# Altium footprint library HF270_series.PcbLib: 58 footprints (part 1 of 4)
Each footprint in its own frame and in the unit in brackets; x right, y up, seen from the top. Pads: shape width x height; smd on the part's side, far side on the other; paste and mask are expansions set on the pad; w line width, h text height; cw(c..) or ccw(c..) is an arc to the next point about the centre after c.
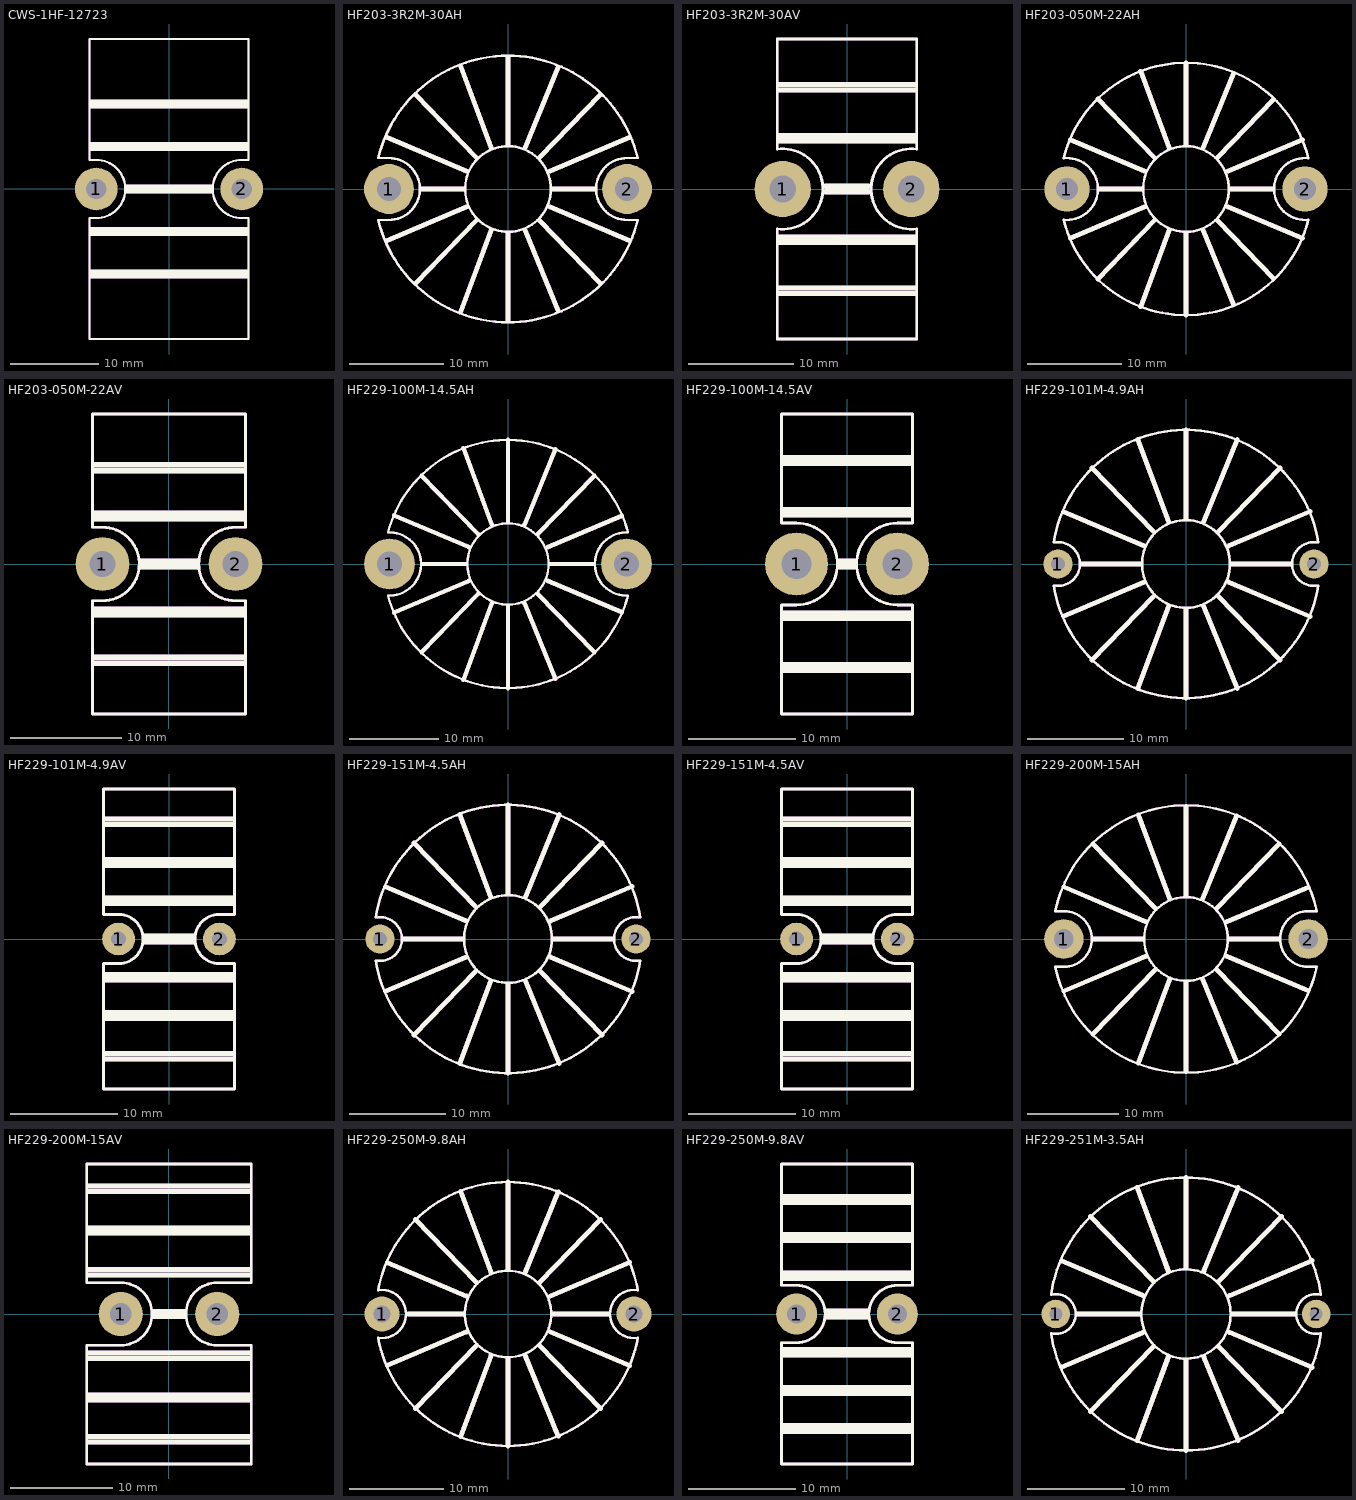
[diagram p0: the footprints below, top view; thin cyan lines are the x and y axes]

## CWS-1HF-12723 [mil]
pads (2):
  round 190 hole 90: 1(-325,0) 2(325,0)
Top Overlay:
  lines w10: -355,-670 -355,-130 -325,-130 ccw(c-325,0) -325,130 -355,130 -355,670 355,670 355,130 325,130 ccw(c325,0) 325,-130 355,-130 355,-670 -355,-670
  lines w19.68: -350,-390 350,-390 ; -350,-370 350,-370 ; -350,-200 350,-200 ; -350,-180 350,-180 ; -350,180 350,180 ; -350,200 350,200 ; -350,370 350,370 ; -350,390 350,390 ; -190,-10 190,-10 ; -190,10 190,10
Mechanical 29:
  lines w10: -355,-670 -355,-130 -325,-130 ccw(c-325,0) -325,130 -355,130 -355,670 355,670 355,130 325,130 ccw(c325,0) 325,-130 355,-130 355,-670 -355,-670
  lines w19.68: -350,-390 350,-390 ; -350,-370 350,-370 ; -350,-200 350,-200 ; -350,-180 350,-180 ; -350,180 350,180 ; -350,200 350,200 ; -350,370 350,370 ; -350,390 350,390 ; -190,-10 190,-10 ; -190,10 190,10
  text "'.Designator'" at -700,275.15 h400

## HF203-3R2M-30AH [mil]
pads (2):
  round 210 hole 100: 1(-500,0) 2(500,0)
Top Overlay:
  circle w10: c0,0 r180
  lines w10: -544.69,-130.06 ccw(c0,0) 544.45,-131.07 ; -544.69,130.06 cw(c0,0) 544.45,131.07 ; -544.45,-130 -500,-130 ccw(c-500,0) -500,130 -544.45,130 ; 544.45,-130 500,-130 cw(c500,0) 500,130 544.45,130
  lines w19.68: -509.12,-217.08 -173.05,-74.68 ; -509.12,217.08 -173.05,74.68 ; -388.47,-396.48 -132.7,-132.43 ; -388.47,396.48 -132.7,132.43 ; -365,0 -185,0 ; -198.53,-515.55 -70.44,-171.87 ; -198.53,515.55 -70.44,171.87 ; 0,-555 0,-185 ; 0,185 0,555 ; 72.46,-173.99 210.86,-511.7 ; 72.46,173.99 210.86,511.7 ; 132.5,-132.5 388.45,-396.51 ; 132.5,132.5 388.45,396.51 ; 175.3,-74.28 511.4,-216.7 ; 175.3,74.28 511.4,216.7 ; 185,0 365,0
Mechanical 29:
  circle w10: c0,0 r180
  lines w10: -544.69,-130.06 ccw(c0,0) 544.45,-131.07 ; -544.69,130.06 cw(c0,0) 544.45,131.07 ; -544.45,-130 -500,-130 ccw(c-500,0) -500,130 -544.45,130 ; 544.45,-130 500,-130 cw(c500,0) 500,130 544.45,130
  lines w19.68: -509.12,-217.08 -173.05,-74.68 ; -509.12,217.08 -173.05,74.68 ; -388.47,-396.48 -132.7,-132.43 ; -388.47,396.48 -132.7,132.43 ; -365,0 -185,0 ; -198.53,-515.55 -70.44,-171.87 ; -198.53,515.55 -70.44,171.87 ; 0,-555 0,-185 ; 0,185 0,555 ; 72.46,-173.99 210.86,-511.7 ; 72.46,173.99 210.86,511.7 ; 132.5,-132.5 388.45,-396.51 ; 132.5,132.5 388.45,396.51 ; 175.3,-74.28 511.4,-216.7 ; 175.3,74.28 511.4,216.7 ; 185,0 365,0
  text "'.Designator'" at -290,145.15 h400

## HF203-3R2M-30AV [mil]
pads (2):
  round 210 hole 100: 1(-240,0) 2(240,0)
Top Overlay:
  lines w10: -260.1,-148.65 ccw(c-240,0) -260,148.66 ; -260,-147.9 -260,-560 260,-560 260,-147.9 ; -260,147.9 -260,560 260,560 260,147.9 ; 260,-148.66 cw(c240,0) 260.1,148.65
  lines w19.68: -255,-390 255,-390 ; -255,-370 255,-370 ; -255,-200 255,-200 ; -255,-180 255,-180 ; -255,180 255,180 ; -255,200 255,200 ; -255,370 255,370 ; -255,390 255,390 ; -80,-10 80,-10 ; -80,10 80,10
Mechanical 29:
  lines w10: -260.1,-148.65 ccw(c-240,0) -260,148.66 ; -260,-147.9 -260,-560 260,-560 260,-147.9 ; -260,147.9 -260,560 260,560 260,147.9 ; 260,-148.66 cw(c240,0) 260.1,148.65
  lines w19.68: -255,-390 255,-390 ; -255,-370 255,-370 ; -255,-200 255,-200 ; -255,-180 255,-180 ; -255,180 255,180 ; -255,200 255,200 ; -255,370 255,370 ; -255,390 255,390 ; -80,-10 80,-10 ; -80,10 80,10
  text "'.Designator'" at -1750,-64.85 h400

## HF203-050M-22AH [mil]
pads (2):
  round 190 hole 93: 1(-500,0) 2(500,0)
Top Overlay:
  circle w10: c0,0 r180
  lines w10: -513.95,129.44 cw(c0,0) 513.58,130.91 ; -513.41,129.31 cw(c-500,0) -514,-129.24 ccw(c0,0) 514,-129.24 ; 513.41,129.31 ccw(c500,0) 514.25,-129.22
  lines w19.68: -486.13,-207.34 -173.05,-74.68 ; -486.13,207.34 -173.05,74.68 ; -371.29,-378.75 -132.7,-132.43 ; -371.29,378.75 -132.7,132.43 ; -365,0 -185,0 ; -190.76,-494.72 -70.44,-171.87 ; -190.76,494.72 -70.44,171.87 ; 0,-530 0,-185 ; 0,185 0,530 ; 72.46,-173.99 200.65,-486.78 ; 72.46,173.99 200.65,486.78 ; 132.5,-132.5 368.84,-376.28 ; 132.5,132.5 368.84,376.28 ; 175.3,-74.28 489.06,-207.23 ; 175.3,74.28 489.06,207.23 ; 185,0 365,0
Mechanical 29:
  circle w10: c0,0 r180
  lines w10: -513.95,129.44 cw(c0,0) 513.58,130.91 ; -513.41,129.31 cw(c-500,0) -514,-129.24 ccw(c0,0) 514,-129.24 ; 513.41,129.31 ccw(c500,0) 514.25,-129.22
  lines w19.68: -486.13,-207.34 -173.05,-74.68 ; -486.13,207.34 -173.05,74.68 ; -371.29,-378.75 -132.7,-132.43 ; -371.29,378.75 -132.7,132.43 ; -365,0 -185,0 ; -190.76,-494.72 -70.44,-171.87 ; -190.76,494.72 -70.44,171.87 ; 0,-530 0,-185 ; 0,185 0,530 ; 72.46,-173.99 200.65,-486.78 ; 72.46,173.99 200.65,486.78 ; 132.5,-132.5 368.84,-376.28 ; 132.5,132.5 368.84,376.28 ; 175.3,-74.28 489.06,-207.23 ; 175.3,74.28 489.06,207.23 ; 185,0 365,0
  text "'.Designator'" at -290,145.15 h400

## HF203-050M-22AV [mil]
pads (2):
  round 190 hole 93: 1(-235,0) 2(235,0)
Top Overlay:
  lines w10: -270,-130 -270,-530 270,-530 270,-130 ; -266,-130 -235,-130 ccw(c-235,0) -235,130 -270,130 -270,530 270,530 270,130 235,130 ccw(c235,0) 235,-130 266,-130
  lines w19.68: -265.5,-350 264.5,-350 ; -265.5,350 264.5,350 ; -265,-180 265,-180 ; -265,180 265,180 ; -264.5,-330 264.5,-330 ; -264.5,330 264.5,330 ; -264,-160 265,-160 ; -264,160 265,160 ; -101,-10 101,-10 ; -100,10 101,10
Mechanical 29:
  lines w10: -270,-130 -270,-530 270,-530 270,-130 ; -266,-130 -235,-130 ccw(c-235,0) -235,130 -270,130 -270,530 270,530 270,130 235,130 ccw(c235,0) 235,-130 266,-130
  lines w19.68: -265.5,-350 264.5,-350 ; -265.5,350 264.5,350 ; -265,-180 265,-180 ; -265,180 265,180 ; -264.5,-330 264.5,-330 ; -264.5,330 264.5,330 ; -264,-160 265,-160 ; -264,160 265,160 ; -101,-10 101,-10 ; -100,10 101,10
  text "'.Designator'" at -1750,-64.85 h400

## HF229-100M-14.5AH [mil]
pads (2):
  round 225 hole 110: 1(-525,0) 2(525,0)
Top Overlay:
  circle w10: c0,0 r180
  lines w10: -531.88,-140 ccw(c0,0) 531.43,-141.71 ; -531.88,140 cw(c0,0) 531.43,141.71 ; -531.34,-139.86 ccw(c-525,0) -531.34,139.86 ; 531.34,-139.86 cw(c525,0) 531.34,139.86
  lines w19.68: -504.88,-215.28 -173.05,-74.68 ; -504.88,215.28 -173.05,74.68 ; -383.55,-391.4 -132.7,-132.43 ; -383.55,391.4 -132.7,132.43 ; -380,0 -185,0 ; -197.92,-513.91 -70.44,-171.87 ; -197.92,513.91 -70.44,171.87 ; 0,-550 0,-185 ; 0,185 0,550 ; 72.46,-173.99 210.14,-509.94 ; 72.46,173.99 210.14,509.94 ; 132.5,-132.5 383.6,-391.51 ; 132.5,132.5 383.6,391.51 ; 175.3,-74.28 505.37,-214.14 ; 175.3,74.28 505.37,214.14 ; 185,0 380,0
Mechanical 29:
  circle w10: c0,0 r180
  lines w10: -531.88,-140 ccw(c0,0) 531.43,-141.71 ; -531.88,140 cw(c0,0) 531.43,141.71 ; -531.34,-139.86 ccw(c-525,0) -531.34,139.86 ; 531.34,-139.86 cw(c525,0) 531.34,139.86
  lines w19.68: -504.88,-215.28 -173.05,-74.68 ; -504.88,215.28 -173.05,74.68 ; -383.55,-391.4 -132.7,-132.43 ; -383.55,391.4 -132.7,132.43 ; -380,0 -185,0 ; -197.92,-513.91 -70.44,-171.87 ; -197.92,513.91 -70.44,171.87 ; 0,-550 0,-185 ; 0,185 0,550 ; 72.46,-173.99 210.14,-509.94 ; 72.46,173.99 210.14,509.94 ; 132.5,-132.5 383.6,-391.51 ; 132.5,132.5 383.6,391.51 ; 175.3,-74.28 505.37,-214.14 ; 175.3,74.28 505.37,214.14 ; 185,0 380,0
  text "'.Designator'" at -290,145.15 h400

## HF229-100M-14.5AV [mil]
pads (2):
  round 230 hole 110: 1(-185,0) 2(185,0)
Top Overlay:
  lines w10: -240,-550 240,-550 240,-150 185,-150 cw(c185,0) 185,150 240,150 240,550 -240,550 -240,150 -185,150 cw(c-185,0) -185,-150 -240,-150 -240,-550
  lines w19.68: -235,-390 235,-390 ; -235,-370 235,-370 ; -235,-200 235,-200 ; -235,-180 235,-180 ; -235,180 235,180 ; -235,200 235,200 ; -235,370 235,370 ; -235,390 235,390 ; -30,-10 30,-10 ; -30,10 30,10
Mechanical 29:
  lines w10: -240,-550 240,-550 240,-150 185,-150 cw(c185,0) 185,150 240,150 240,550 -240,550 -240,150 -185,150 cw(c-185,0) -185,-150 -240,-150 -240,-550
  lines w19.68: -235,-390 235,-390 ; -235,-370 235,-370 ; -235,-200 235,-200 ; -235,-180 235,-180 ; -235,180 235,180 ; -235,200 235,200 ; -235,370 235,370 ; -235,390 235,390 ; -30,-10 30,-10 ; -30,10 30,10
  text "'.Designator'" at -1750,-64.85 h400

## HF229-101M-4.9AH [mil]
pads (2):
  round 120 hole 56: 1(-525,0) 2(525,0)
Top Overlay:
  circle w10: c0,0 r180
  lines w10: -542.88,-88.21 ccw(c0,0) 542.88,-88.21 cw(c525,0) 542.88,88.21 ccw(c0,0) -542.88,88.21 cw(c-525,0) -542.88,-88.21
  lines w19.68: -502.44,-214.25 -173.05,-74.68 ; -502.44,214.25 -173.05,74.68 ; -430,0 -185,0 ; -385.97,-393.9 -132.7,-132.43 ; -385.97,393.9 -132.7,132.43 ; -196.89,-511.16 -70.44,-171.87 ; -196.89,511.16 -70.44,171.87 ; 0,-550 0,-185 ; 0,185 0,550 ; 72.46,-173.99 210.14,-509.94 ; 72.46,173.99 210.14,509.94 ; 132.5,-132.5 385.95,-393.93 ; 132.5,132.5 385.95,393.93 ; 175.3,-74.28 507.81,-215.17 ; 175.3,74.28 507.81,215.17 ; 185,0 430,0
Mechanical 29:
  circle w10: c0,0 r180
  lines w10: -542.88,-88.21 ccw(c0,0) 542.88,-88.21 cw(c525,0) 542.88,88.21 ccw(c0,0) -542.88,88.21 cw(c-525,0) -542.88,-88.21
  lines w19.68: -502.44,-214.25 -173.05,-74.68 ; -502.44,214.25 -173.05,74.68 ; -430,0 -185,0 ; -385.97,-393.9 -132.7,-132.43 ; -385.97,393.9 -132.7,132.43 ; -196.89,-511.16 -70.44,-171.87 ; -196.89,511.16 -70.44,171.87 ; 0,-550 0,-185 ; 0,185 0,550 ; 72.46,-173.99 210.14,-509.94 ; 72.46,173.99 210.14,509.94 ; 132.5,-132.5 385.95,-393.93 ; 132.5,132.5 385.95,393.93 ; 175.3,-74.28 507.81,-215.17 ; 175.3,74.28 507.81,215.17 ; 185,0 430,0
  text "'.Designator'" at -290,145.15 h400

## HF229-101M-4.9AV [mil]
pads (2):
  round 120 hole 56: 1(-185,0) 2(185,0)
Top Overlay:
  lines w10: -240,-550 -240,-90 -185,-90 ccw(c-185,0) -185,90 -240,90 -240,550 240,550 240,90 185,90 ccw(c185,0) 185,-90 240,-90 240,-550 -240,-550
  lines w19.68: -235,-440 235,-440 ; -235,-420 235,-420 ; -235,-290 235,-290 ; -235,-270 235,-270 ; -235,-150 235,-150 ; -235,-130 235,-130 ; -235,130 235,130 ; -235,150 235,150 ; -235,270 235,270 ; -235,290 235,290 ; -235,420 235,420 ; -235,440 235,440 ; -90,-10 90,-10 ; -90,10 90,10
Mechanical 29:
  lines w10: -240,-550 -240,-90 -185,-90 ccw(c-185,0) -185,90 -240,90 -240,550 240,550 240,90 185,90 ccw(c185,0) 185,-90 240,-90 240,-550 -240,-550
  lines w19.68: -235,-440 235,-440 ; -235,-420 235,-420 ; -235,-290 235,-290 ; -235,-270 235,-270 ; -235,-150 235,-150 ; -235,-130 235,-130 ; -235,130 235,130 ; -235,150 235,150 ; -235,270 235,270 ; -235,290 235,290 ; -235,420 235,420 ; -235,440 235,440 ; -90,-10 90,-10 ; -90,10 90,10
  text "'.Designator'" at -1750,-64.85 h400

## HF229-151M-4.5AH [mil]
pads (2):
  round 120 hole 56: 1(-525,0) 2(525,0)
Top Overlay:
  circle w10: c0,0 r180
  lines w10: -542.88,-88.21 ccw(c0,0) 542.88,-88.21 cw(c525,0) 542.88,88.21 ccw(c0,0) -542.88,88.21 cw(c-525,0) -542.88,-88.21
  lines w19.68: -502.44,-214.25 -173.05,-74.68 ; -502.44,214.25 -173.05,74.68 ; -430,0 -185,0 ; -385.97,-393.9 -132.7,-132.43 ; -385.97,393.9 -132.7,132.43 ; -196.89,-511.16 -70.44,-171.87 ; -196.89,511.16 -70.44,171.87 ; 0,-550 0,-185 ; 0,185 0,550 ; 72.46,-173.99 210.14,-509.94 ; 72.46,173.99 210.14,509.94 ; 132.5,-132.5 385.95,-393.93 ; 132.5,132.5 385.95,393.93 ; 175.3,-74.28 507.81,-215.17 ; 175.3,74.28 507.81,215.17 ; 185,0 430,0
Mechanical 29:
  circle w10: c0,0 r180
  lines w10: -542.88,-88.21 ccw(c0,0) 542.88,-88.21 cw(c525,0) 542.88,88.21 ccw(c0,0) -542.88,88.21 cw(c-525,0) -542.88,-88.21
  lines w19.68: -502.44,-214.25 -173.05,-74.68 ; -502.44,214.25 -173.05,74.68 ; -430,0 -185,0 ; -385.97,-393.9 -132.7,-132.43 ; -385.97,393.9 -132.7,132.43 ; -196.89,-511.16 -70.44,-171.87 ; -196.89,511.16 -70.44,171.87 ; 0,-550 0,-185 ; 0,185 0,550 ; 72.46,-173.99 210.14,-509.94 ; 72.46,173.99 210.14,509.94 ; 132.5,-132.5 385.95,-393.93 ; 132.5,132.5 385.95,393.93 ; 175.3,-74.28 507.81,-215.17 ; 175.3,74.28 507.81,215.17 ; 185,0 430,0
  text "'.Designator'" at -290,145.15 h400

## HF229-151M-4.5AV [mil]
pads (2):
  round 120 hole 56: 1(-185,0) 2(185,0)
Top Overlay:
  lines w10: -240,-550 240,-550 240,-90 185,-90 cw(c185,0) 185,90 240,90 240,550 -240,550 -240,90 -185,90 cw(c-185,0) -185,-90 -240,-90 -240,-550
  lines w19.68: -235,-440 235,-440 ; -235,-420 235,-420 ; -235,-290 235,-290 ; -235,-270 235,-270 ; -235,-150 235,-150 ; -235,-130 235,-130 ; -235,130 235,130 ; -235,150 235,150 ; -235,270 235,270 ; -235,290 235,290 ; -235,420 235,420 ; -235,440 235,440 ; -90,-10 90,-10 ; -90,10 90,10
Mechanical 29:
  lines w10: -240,-550 240,-550 240,-90 185,-90 cw(c185,0) 185,90 240,90 240,550 -240,550 -240,90 -185,90 cw(c-185,0) -185,-90 -240,-90 -240,-550
  lines w19.68: -235,-440 235,-440 ; -235,-420 235,-420 ; -235,-290 235,-290 ; -235,-270 235,-270 ; -235,-150 235,-150 ; -235,-130 235,-130 ; -235,130 235,130 ; -235,150 235,150 ; -235,270 235,270 ; -235,290 235,290 ; -235,420 235,420 ; -235,440 235,440 ; -90,-10 90,-10 ; -90,10 90,10
  text "'.Designator'" at -1750,-64.85 h400

## HF229-200M-15AH [mil]
pads (2):
  round 170 hole 84: 1(-525,0) 2(525,0)
Top Overlay:
  circle w10: c0,0 r180
  lines w10: -562.32,-120.09 ccw(c0,0) 562.45,-119.46 ; -562.32,120.09 cw(c0,0) 562.45,119.46 ; -561.91,-120 -525,-120 ccw(c-525,0) -525,120 -561.91,120 ; 561.91,-120 525,-120 cw(c525,0) 525,120 561.91,120
  lines w19.68: -525.43,-223.99 -173.05,-74.68 ; -525.43,223.99 -173.05,74.68 ; -400.81,-409.22 -132.7,-132.43 ; -400.81,409.22 -132.7,132.43 ; -400,0 -185,0 ; -205.68,-534.75 -70.44,-171.87 ; -205.68,534.75 -70.44,171.87 ; 0,-570 0,-185 ; 0,185 0,570 ; 72.46,-173.99 218.6,-530.57 ; 72.46,173.99 218.6,530.57 ; 132.5,-132.5 400.79,-409.24 ; 132.5,132.5 400.79,409.24 ; 175.3,-74.28 525.91,-222.84 ; 175.3,74.28 525.91,222.84 ; 185,0 400,0
Mechanical 29:
  circle w10: c0,0 r180
  lines w10: -562.32,-120.09 ccw(c0,0) 562.45,-119.46 ; -562.32,120.09 cw(c0,0) 562.45,119.46 ; -561.91,-120 -525,-120 ccw(c-525,0) -525,120 -561.91,120 ; 561.91,-120 525,-120 cw(c525,0) 525,120 561.91,120
  lines w19.68: -525.43,-223.99 -173.05,-74.68 ; -525.43,223.99 -173.05,74.68 ; -400.81,-409.22 -132.7,-132.43 ; -400.81,409.22 -132.7,132.43 ; -400,0 -185,0 ; -205.68,-534.75 -70.44,-171.87 ; -205.68,534.75 -70.44,171.87 ; 0,-570 0,-185 ; 0,185 0,570 ; 72.46,-173.99 218.6,-530.57 ; 72.46,173.99 218.6,530.57 ; 132.5,-132.5 400.79,-409.24 ; 132.5,132.5 400.79,409.24 ; 175.3,-74.28 525.91,-222.84 ; 175.3,74.28 525.91,222.84 ; 185,0 400,0
  text "'.Designator'" at -290,145.15 h400

## HF229-200M-15AV [mil]
pads (2):
  round 170 hole 84: 1(-185,0) 2(185,0)
Top Overlay:
  lines w10: -315,-575 315,-575 315,-120 185,-120 cw(c185,0) 185,120 314.06,120 315,120.94 315,575 -315,575 -315,120.94 -314.06,120 -185,120 cw(c-185,0) -185,-120 -315,-120 -315,-575
  lines w19.68: -310,-490 310,-490 ; -310,-470 310,-470 ; -310,-330 310,-330 ; -310,-310 310,-310 ; -310,-170 310,-170 ; -310,-150 310,-150 ; -310,150 310,150 ; -310,170 310,170 ; -310,310 310,310 ; -310,330 310,330 ; -310,470 310,470 ; -310,490 310,490 ; -60,-10 60,-10 ; -60,10 60,10
Mechanical 29:
  lines w10: -315,-575 315,-575 315,-120 185,-120 cw(c185,0) 185,120 314.06,120 315,120.94 315,575 -315,575 -315,120.94 -314.06,120 -185,120 cw(c-185,0) -185,-120 -315,-120 -315,-575
  lines w19.68: -310,-490 310,-490 ; -310,-470 310,-470 ; -310,-330 310,-330 ; -310,-310 310,-310 ; -310,-170 310,-170 ; -310,-150 310,-150 ; -310,150 310,150 ; -310,170 310,170 ; -310,310 310,310 ; -310,330 310,330 ; -310,470 310,470 ; -310,490 310,490 ; -60,-10 60,-10 ; -60,10 60,10
  text "'.Designator'" at -1750,-64.85 h400

## HF229-250M-9.8AH [mil]
pads (2):
  round 145 hole 71: 1(-525,0) 2(525,0)
Top Overlay:
  circle w10: c0,0 r180
  lines w10: -540.97,-99.25 ccw(c0,0) 540.97,-99.25 ; -540.89,-98.73 ccw(c-525,0) -540.76,98.75 ; -540.9,99.63 cw(c0,0) 540.9,99.63 ; 540.76,98.75 ccw(c525,0) 540.89,-98.73
  lines w19.68: -502.44,-214.25 -173.05,-74.68 ; -502.44,214.25 -173.05,74.68 ; -415,0 -185,0 ; -385.97,-393.9 -132.7,-132.43 ; -385.97,393.9 -132.7,132.43 ; -196.89,-511.16 -70.44,-171.87 ; -196.89,511.16 -70.44,171.87 ; 0,-550 0,-185 ; 0,185 0,550 ; 72.46,-173.99 210.14,-509.94 ; 72.46,173.99 210.14,509.94 ; 132.5,-132.5 385.95,-393.93 ; 132.5,132.5 385.95,393.93 ; 175.3,-74.28 507.81,-215.17 ; 175.3,74.28 507.81,215.17 ; 185,0 420,0
Mechanical 29:
  circle w10: c0,0 r180
  lines w10: -540.97,-99.25 ccw(c0,0) 540.97,-99.25 ; -540.89,-98.73 ccw(c-525,0) -540.76,98.75 ; -540.9,99.63 cw(c0,0) 540.9,99.63 ; 540.76,98.75 ccw(c525,0) 540.89,-98.73
  lines w19.68: -502.44,-214.25 -173.05,-74.68 ; -502.44,214.25 -173.05,74.68 ; -415,0 -185,0 ; -385.97,-393.9 -132.7,-132.43 ; -385.97,393.9 -132.7,132.43 ; -196.89,-511.16 -70.44,-171.87 ; -196.89,511.16 -70.44,171.87 ; 0,-550 0,-185 ; 0,185 0,550 ; 72.46,-173.99 210.14,-509.94 ; 72.46,173.99 210.14,509.94 ; 132.5,-132.5 385.95,-393.93 ; 132.5,132.5 385.95,393.93 ; 175.3,-74.28 507.81,-215.17 ; 175.3,74.28 507.81,215.17 ; 185,0 420,0
  text "'.Designator'" at -900,275.15 h400

## HF229-250M-9.8AV [mil]
pads (2):
  round 150 hole 71: 1(-185,0) 2(185,0)
Top Overlay:
  lines w10: -240,105 -240,550 240,550 240,105 ; -235,105 -185,105 cw(c-185,0) -185,-105 -240,-105 -240,-550 240,-550 240,-105 185,-105 cw(c185,0) 185,105 235,105
  lines w19.68: -235,-430 235,-430 ; -235,-410 235,-410 ; -235,-290 235,-290 ; -235,-270 235,-270 ; -235,-150 235,-150 ; -235,-130 235,-130 ; -235,130 235,130 ; -235,150 235,150 ; -235,270 235,270 ; -235,290 235,290 ; -235,410 235,410 ; -235,430 235,430 ; -75,-10 75,-10 ; -75,10 75,10
Mechanical 29:
  lines w10: -240,105 -240,550 240,550 240,105 ; -235,105 -185,105 cw(c-185,0) -185,-105 -240,-105 -240,-550 240,-550 240,-105 185,-105 cw(c185,0) 185,105 235,105
  lines w19.68: -235,-430 235,-430 ; -235,-410 235,-410 ; -235,-290 235,-290 ; -235,-270 235,-270 ; -235,-150 235,-150 ; -235,-130 235,-130 ; -235,130 235,130 ; -235,150 235,150 ; -235,270 235,270 ; -235,290 235,290 ; -235,410 235,410 ; -235,430 235,430 ; -75,-10 75,-10 ; -75,10 75,10
  text "'.Designator'" at -1200,175.15 h400

## HF229-251M-3.5AH [mil]
pads (2):
  round 115 hole 52: 1(-525,0) 2(525,0)
Top Overlay:
  circle w10: c0,0 r180
  lines w10: -544.18,-79.79 ccw(c0,0) 544.18,-79.79 ; -544.18,79.79 cw(c0,0) 544.18,79.79 ; -543.7,-77.78 ccw(c-525,0) -543.7,77.78 ; 543.7,-77.78 cw(c525,0) 543.7,77.78
  lines w19.68: -502.44,-214.25 -173.05,-74.68 ; -502.44,214.25 -173.05,74.68 ; -440,0 -185,0 ; -385.97,-393.9 -132.7,-132.43 ; -385.97,393.9 -132.7,132.43 ; -196.89,-511.16 -70.44,-171.87 ; -196.89,511.16 -70.44,171.87 ; 0,-550 0,-185 ; 0,185 0,550 ; 72.46,-173.99 210.14,-509.94 ; 72.46,173.99 210.14,509.94 ; 132.5,-132.5 385.95,-393.93 ; 132.5,132.5 385.95,393.93 ; 175.3,-74.28 507.81,-215.17 ; 175.3,74.28 507.81,215.17 ; 185,0 440,0
Mechanical 29:
  circle w10: c0,0 r180
  lines w10: -544.18,-79.79 ccw(c0,0) 544.18,-79.79 ; -544.18,79.79 cw(c0,0) 544.18,79.79 ; -543.7,-77.78 ccw(c-525,0) -543.7,77.78 ; 543.7,-77.78 cw(c525,0) 543.7,77.78
  lines w19.68: -502.44,-214.25 -173.05,-74.68 ; -502.44,214.25 -173.05,74.68 ; -440,0 -185,0 ; -385.97,-393.9 -132.7,-132.43 ; -385.97,393.9 -132.7,132.43 ; -196.89,-511.16 -70.44,-171.87 ; -196.89,511.16 -70.44,171.87 ; 0,-550 0,-185 ; 0,185 0,550 ; 72.46,-173.99 210.14,-509.94 ; 72.46,173.99 210.14,509.94 ; 132.5,-132.5 385.95,-393.93 ; 132.5,132.5 385.95,393.93 ; 175.3,-74.28 507.81,-215.17 ; 175.3,74.28 507.81,215.17 ; 185,0 440,0
  text "'.Designator'" at -900,275.15 h400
